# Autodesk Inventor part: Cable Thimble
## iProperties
Title: Cable Thimble
Author: QBZ
Shininess: 41.0
PropertySet Name: _Private Model Information
Created: 2001-02
Part Number: Cable Thimble
Document SubType Name: Modeling
Designer: QBZ
Material: Steel, Mild
Catalog Web Link: http://www.thecrosbygroup.com
Description: 1/2 ST Cable Thimble
Vendor: Crosby
Control State: 0
Master: False
Checked Out: False
PropertySet Name: Design Tracking Control
Density: 7.86
Volumn: 2.686211023356322
Area: 40.07138888349642
PropertySet Name: Model Information
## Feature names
1. Sweep2
2. Extrusion1
